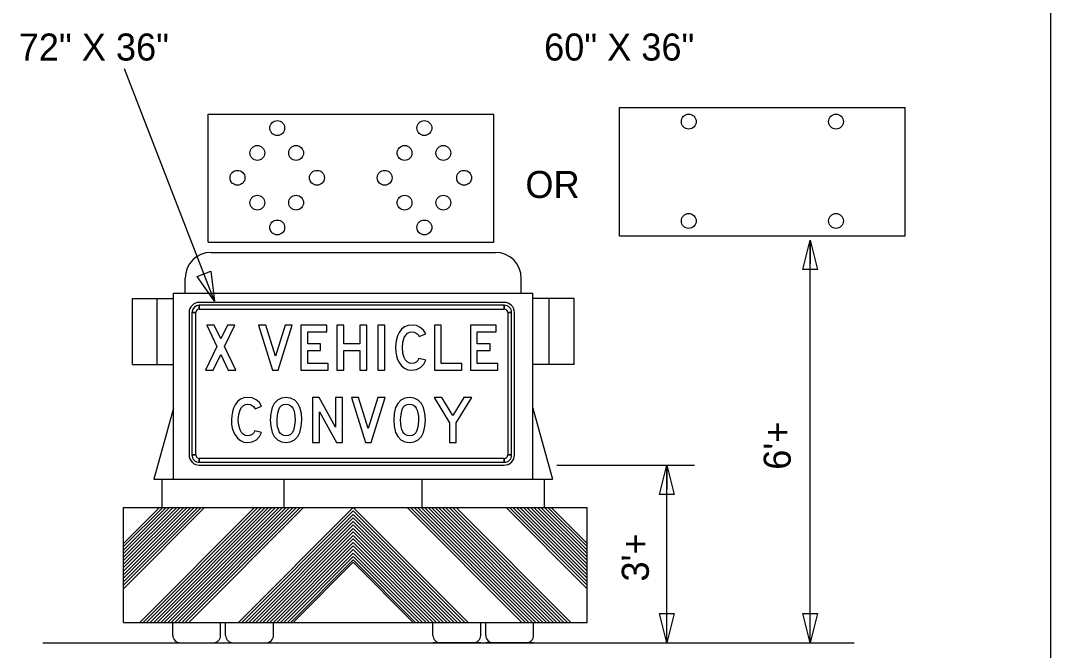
# Model space of a CAD drawing. Extents: x 1374027 to 1374537, y 380415 to 381405.
# Drawn here: x 1374118.45 to 1374141.31, y 381351.11 to 381365.09 of the extents above; entities that cross this region are included whole.
import ezdxf

# ---------------------------------------------------------------- set-up
doc = ezdxf.new("R2010")
doc.units = 0
doc.layers.add('Working Level 1', color=7, linetype='Continuous')

msp = doc.modelspace()

# ---------------------------------------------------------------- linework, layer by layer
at = {"layer": 'Working Level 1'}
for p, q in [((1374141.313, 381402.674), (1374141.313, 381297.674)), ((1374122.756, 381358.864), (1374120.755, 381364.019)), ((1374131.749, 381360.313), (1374131.749, 381363.157)), ((1374131.749, 381363.157), (1374138.092, 381363.157)), ((1374138.092, 381360.313), (1374138.092, 381363.157)), ((1374122.611, 381363.012), (1374128.954, 381363.012)), ((1374122.611, 381360.168), (1374122.611, 381363.012)), ((1374128.954, 381360.168), (1374128.954, 381363.012)), ((1374131.749, 381360.313), (1374138.092, 381360.313)), ((1374122.611, 381360.168), (1374128.954, 381360.168)), ((1374135.976, 381351.279), (1374135.976, 381360.211)), ((1374135.976, 381360.211), (1374135.976, 381359.687)), ((1374122.676, 381359.943), (1374128.99, 381359.943)), ((1374122.102, 381359.04), (1374122.102, 381359.369)), ((1374129.565, 381359.04), (1374129.565, 381359.369)), ((1374121.842, 381354.913), (1374121.842, 381359.04)), ((1374121.842, 381359.04), (1374129.825, 381359.04)), ((1374129.825, 381354.913), (1374129.825, 381359.04)), ((1374120.931, 381357.457), (1374120.931, 381358.923)), ((1374120.931, 381358.923), (1374121.842, 381358.923)), ((1374121.483, 381357.457), (1374121.483, 381358.923)), ((1374129.188, 381358.833), (1374122.416, 381358.833)), ((1374122.416, 381358.682), (1374122.416, 381358.77)), ((1374129.188, 381358.77), (1374129.188, 381358.682)), ((1374130.736, 381358.923), (1374129.825, 381358.923)), ((1374130.184, 381357.457), (1374130.184, 381358.923)), ((1374130.736, 381357.457), (1374130.736, 381358.923)), ((1374122.191, 381358.607), (1374122.191, 381355.447)), ((1374122.253, 381358.607), (1374122.341, 381358.607)), ((1374129.263, 381358.607), (1374129.351, 381358.607)), ((1374129.414, 381355.447), (1374129.414, 381358.607)), ((1374120.931, 381357.457), (1374121.842, 381357.457)), ((1374130.736, 381357.457), (1374129.825, 381357.457)), ((1374121.842, 381356.485), (1374121.41, 381354.913)), ((1374129.825, 381356.485), (1374130.256, 381354.913)), ((1374122.341, 381355.447), (1374122.253, 381355.447)), ((1374122.416, 381355.284), (1374122.416, 381355.372)), ((1374129.188, 381355.372), (1374129.188, 381355.284)), ((1374129.351, 381355.447), (1374129.263, 381355.447)), ((1374122.416, 381355.221), (1374129.188, 381355.221)), ((1374130.351, 381355.221), (1374133.413, 381355.221)), ((1374132.795, 381351.279), (1374132.795, 381355.221)), ((1374132.795, 381355.221), (1374132.795, 381354.689)), ((1374121.41, 381354.913), (1374130.256, 381354.913)), ((1374121.59, 381354.283), (1374121.59, 381354.913)), ((1374124.302, 381354.283), (1374124.302, 381354.902)), ((1374127.365, 381354.283), (1374127.365, 381354.902)), ((1374130.077, 381354.283), (1374130.077, 381354.913)), ((1374120.733, 381354.283), (1374131.028, 381354.283)), ((1374120.733, 381354.283), (1374131.028, 381354.283)), ((1374120.733, 381354.283), (1374131.028, 381354.283)), ((1374120.733, 381354.283), (1374131.028, 381354.283)), ((1374120.733, 381351.733), (1374120.733, 381354.283)), ((1374120.733, 381353.485), (1374121.531, 381354.283)), ((1374120.733, 381352.557), (1374122.459, 381354.283)), ((1374120.733, 381352.635), (1374122.38, 381354.283)), ((1374120.733, 381352.713), (1374122.302, 381354.283)), ((1374120.733, 381352.79), (1374122.225, 381354.283)), ((1374120.733, 381352.868), (1374122.147, 381354.283)), ((1374120.733, 381352.947), (1374122.069, 381354.283)), ((1374120.733, 381353.024), (1374121.992, 381354.283)), ((1374120.733, 381353.102), (1374121.914, 381354.283)), ((1374120.733, 381353.18), (1374121.836, 381354.283)), ((1374120.733, 381353.258), (1374121.758, 381354.283)), ((1374120.733, 381353.335), (1374121.681, 381354.283)), ((1374120.733, 381353.413), (1374121.603, 381354.283)), ((1374120.733, 381352.48), (1374122.534, 381354.281)), ((1374121.092, 381351.733), (1374123.642, 381354.283)), ((1374121.169, 381351.733), (1374123.719, 381354.283)), ((1374121.247, 381351.733), (1374123.797, 381354.283)), ((1374121.326, 381351.733), (1374123.875, 381354.283)), ((1374121.403, 381351.733), (1374123.952, 381354.283)), ((1374121.481, 381351.733), (1374124.03, 381354.283)), ((1374121.559, 381351.733), (1374124.109, 381354.283)), ((1374121.637, 381351.733), (1374124.187, 381354.283)), ((1374121.714, 381351.733), (1374124.264, 381354.283)), ((1374121.792, 381351.733), (1374124.342, 381354.283)), ((1374121.87, 381351.733), (1374124.42, 381354.283)), ((1374121.947, 381351.733), (1374124.497, 381354.283)), ((1374122.025, 381351.733), (1374124.575, 381354.283)), ((1374122.103, 381351.733), (1374124.652, 381354.282)), ((1374122.181, 381351.733), (1374124.731, 381354.283)), ((1374123.284, 381351.733), (1374125.833, 381354.283)), ((1374123.361, 381351.733), (1374125.833, 381354.205)), ((1374128.383, 381351.733), (1374125.833, 381354.283)), ((1374128.302, 381351.738), (1374125.833, 381354.205)), ((1374129.579, 381351.733), (1374127.03, 381354.283)), ((1374129.657, 381351.733), (1374127.108, 381354.282)), ((1374129.735, 381351.733), (1374127.185, 381354.283)), ((1374129.813, 381351.733), (1374127.263, 381354.283)), ((1374129.89, 381351.733), (1374127.34, 381354.283)), ((1374129.968, 381351.733), (1374127.418, 381354.283)), ((1374130.046, 381351.733), (1374127.497, 381354.283)), ((1374130.123, 381351.733), (1374127.574, 381354.283)), ((1374130.201, 381351.733), (1374127.652, 381354.283)), ((1374130.28, 381351.733), (1374127.73, 381354.283)), ((1374130.358, 381351.733), (1374127.808, 381354.283)), ((1374130.435, 381351.733), (1374127.885, 381354.283)), ((1374130.513, 381351.733), (1374127.963, 381354.283)), ((1374130.591, 381351.733), (1374128.041, 381354.283)), ((1374130.668, 381351.733), (1374128.119, 381354.283)), ((1374131.028, 381352.48), (1374129.226, 381354.281)), ((1374131.028, 381352.557), (1374129.302, 381354.283)), ((1374131.028, 381352.635), (1374129.38, 381354.283)), ((1374131.028, 381352.713), (1374129.458, 381354.283)), ((1374131.028, 381352.79), (1374129.535, 381354.283)), ((1374131.028, 381352.868), (1374129.613, 381354.283)), ((1374131.028, 381352.947), (1374129.691, 381354.283)), ((1374131.028, 381353.024), (1374129.768, 381354.283)), ((1374131.028, 381353.102), (1374129.846, 381354.283)), ((1374131.028, 381353.18), (1374129.924, 381354.283)), ((1374131.028, 381353.258), (1374130.002, 381354.283)), ((1374131.028, 381353.335), (1374130.079, 381354.283)), ((1374131.028, 381353.413), (1374130.157, 381354.283)), ((1374131.028, 381353.485), (1374130.23, 381354.283)), ((1374131.028, 381351.733), (1374131.028, 381354.283)), ((1374123.439, 381351.733), (1374125.833, 381354.127)), ((1374123.517, 381351.733), (1374125.833, 381354.049)), ((1374123.594, 381351.733), (1374125.833, 381353.972)), ((1374128.228, 381351.733), (1374125.833, 381354.127)), ((1374128.15, 381351.733), (1374125.833, 381354.049)), ((1374128.073, 381351.733), (1374125.833, 381353.972)), ((1374123.672, 381351.733), (1374125.833, 381353.894)), ((1374123.751, 381351.733), (1374125.833, 381353.816)), ((1374123.828, 381351.733), (1374125.833, 381353.739)), ((1374127.995, 381351.733), (1374125.833, 381353.894)), ((1374127.917, 381351.733), (1374125.833, 381353.816)), ((1374127.84, 381351.733), (1374125.833, 381353.739)), ((1374123.906, 381351.733), (1374125.833, 381353.661)), ((1374123.984, 381351.733), (1374125.833, 381353.583)), ((1374124.062, 381351.733), (1374125.833, 381353.505)), ((1374127.762, 381351.733), (1374125.833, 381353.661)), ((1374127.684, 381351.733), (1374125.833, 381353.583)), ((1374127.605, 381351.733), (1374125.833, 381353.505)), ((1374124.139, 381351.733), (1374125.833, 381353.428)), ((1374124.217, 381351.733), (1374125.833, 381353.35)), ((1374124.295, 381351.733), (1374125.833, 381353.272)), ((1374127.528, 381351.733), (1374125.833, 381353.428)), ((1374127.45, 381351.733), (1374125.833, 381353.35)), ((1374127.372, 381351.733), (1374125.833, 381353.272)), ((1374124.372, 381351.733), (1374125.833, 381353.195)), ((1374124.45, 381351.733), (1374125.833, 381353.117)), ((1374124.515, 381351.748), (1374125.833, 381353.066)), ((1374127.295, 381351.733), (1374125.833, 381353.195)), ((1374127.217, 381351.733), (1374125.833, 381353.117)), ((1374127.167, 381351.733), (1374125.833, 381353.066)), ((1374120.733, 381351.733), (1374131.028, 381351.733)), ((1374120.733, 381351.733), (1374131.028, 381351.733)), ((1374120.733, 381351.733), (1374131.028, 381351.733)), ((1374120.733, 381351.733), (1374131.028, 381351.733)), ((1374121.827, 381351.444), (1374121.827, 381351.733)), ((1374122.89, 381351.444), (1374122.89, 381351.733)), ((1374123, 381351.444), (1374123, 381351.733)), ((1374124.064, 381351.444), (1374124.064, 381351.733)), ((1374127.603, 381351.444), (1374127.603, 381351.733)), ((1374128.666, 381351.444), (1374128.666, 381351.733)), ((1374128.776, 381351.444), (1374128.776, 381351.733)), ((1374129.84, 381351.444), (1374129.84, 381351.733)), ((1374118.945, 381351.279), (1374136.956, 381351.279)), ((1374121.827, 381351.279), (1374122.89, 381351.279)), ((1374121.827, 381351.279), (1374122.89, 381351.279)), ((1374121.827, 381351.279), (1374122.89, 381351.279)), ((1374121.827, 381351.279), (1374122.89, 381351.279)), ((1374123, 381351.279), (1374124.064, 381351.279)), ((1374123, 381351.279), (1374124.064, 381351.279)), ((1374123, 381351.279), (1374124.064, 381351.279)), ((1374123, 381351.279), (1374124.064, 381351.279)), ((1374128.666, 381351.279), (1374127.603, 381351.279)), ((1374128.666, 381351.279), (1374127.603, 381351.279)), ((1374128.666, 381351.279), (1374127.603, 381351.279)), ((1374128.666, 381351.279), (1374127.603, 381351.279)), ((1374129.84, 381351.279), (1374128.776, 381351.279)), ((1374129.84, 381351.279), (1374128.776, 381351.279)), ((1374129.84, 381351.279), (1374128.776, 381351.279)), ((1374129.84, 381351.279), (1374128.776, 381351.279))]:
    msp.add_line(p, q, dxfattribs=at)
for points in [[(1374135.814, 381359.561), (1374135.976, 381360.211), (1374136.139, 381359.561)], [(1374122.672, 381359.529), (1374122.756, 381358.864), (1374122.369, 381359.411)], [(1374129.188, 381358.77), (1374122.416, 381358.77), (1374122.416, 381358.682), (1374129.188, 381358.682), (1374129.188, 381358.77)], [(1374122.253, 381358.607), (1374122.253, 381355.447), (1374122.341, 381355.447), (1374122.341, 381358.607), (1374122.253, 381358.607)], [(1374129.351, 381355.447), (1374129.351, 381358.607), (1374129.263, 381358.607), (1374129.263, 381355.447), (1374129.351, 381355.447)], [(1374123.227, 381357.328), (1374122.977, 381357.853), (1374123.206, 381358.331), (1374123.039, 381358.331), (1374122.893, 381358.028), (1374122.749, 381358.331), (1374122.581, 381358.331), (1374122.809, 381357.852), (1374122.557, 381357.328), (1374122.725, 381357.328), (1374122.892, 381357.677), (1374123.059, 381357.328)], [(1374124.48, 381358.331), (1374124.322, 381358.331), (1374124.106, 381357.638), (1374123.891, 381358.331), (1374123.733, 381358.331), (1374124.044, 381357.328), (1374124.168, 381357.328)], [(1374125.28, 381357.479), (1374124.825, 381357.479), (1374124.825, 381357.763), (1374125.109, 381357.763), (1374125.109, 381357.915), (1374124.825, 381357.915), (1374124.825, 381358.18), (1374125.249, 381358.18), (1374125.249, 381358.331), (1374124.673, 381358.331), (1374124.673, 381357.328), (1374125.28, 381357.328)], [(1374126.135, 381357.328), (1374126.135, 381358.331), (1374125.984, 381358.331), (1374125.984, 381357.915), (1374125.624, 381357.915), (1374125.624, 381358.331), (1374125.473, 381358.331), (1374125.473, 381357.328), (1374125.624, 381357.328), (1374125.624, 381357.763), (1374125.984, 381357.763), (1374125.984, 381357.328)], [(1374126.533, 381357.328), (1374126.533, 381358.331), (1374126.382, 381358.331), (1374126.382, 381357.328)], [(1374127.443, 381357.551), (1374127.292, 381357.589), (1374127.269, 381357.545), (1374127.233, 381357.51), (1374127.186, 381357.487), (1374127.133, 381357.479), (1374127.081, 381357.487), (1374127.035, 381357.511), (1374126.997, 381357.551), (1374126.967, 381357.607), (1374126.935, 381357.71), (1374126.925, 381357.83), (1374126.936, 381357.95), (1374126.968, 381358.053), (1374126.999, 381358.108), (1374127.038, 381358.148), (1374127.084, 381358.172), (1374127.138, 381358.18), (1374127.188, 381358.173), (1374127.234, 381358.152), (1374127.272, 381358.119), (1374127.298, 381358.077), (1374127.443, 381358.134), (1374127.394, 381358.215), (1374127.323, 381358.277), (1374127.236, 381358.318), (1374127.141, 381358.331), (1374127.052, 381358.321), (1374126.975, 381358.289), (1374126.909, 381358.237), (1374126.855, 381358.164), (1374126.819, 381358.091), (1374126.794, 381358.012), (1374126.779, 381357.925), (1374126.774, 381357.83), (1374126.779, 381357.736), (1374126.794, 381357.649), (1374126.819, 381357.569), (1374126.854, 381357.497), (1374126.907, 381357.423), (1374126.972, 381357.37), (1374127.048, 381357.338), (1374127.136, 381357.328), (1374127.238, 381357.343), (1374127.329, 381357.39), (1374127.401, 381357.461)], [(1374128.243, 381357.328), (1374128.243, 381357.479), (1374127.787, 381357.479), (1374127.787, 381358.331), (1374127.636, 381358.331), (1374127.636, 381357.328)], [(1374129.042, 381357.479), (1374128.587, 381357.479), (1374128.587, 381357.763), (1374128.871, 381357.763), (1374128.871, 381357.915), (1374128.587, 381357.915), (1374128.587, 381358.18), (1374129.011, 381358.18), (1374129.011, 381358.331), (1374128.436, 381358.331), (1374128.436, 381357.328), (1374129.042, 381357.328)], [(1374123.799, 381355.946), (1374123.647, 381355.984), (1374123.625, 381355.94), (1374123.588, 381355.905), (1374123.541, 381355.882), (1374123.489, 381355.874), (1374123.436, 381355.882), (1374123.391, 381355.906), (1374123.353, 381355.946), (1374123.322, 381356.002), (1374123.291, 381356.105), (1374123.281, 381356.224), (1374123.291, 381356.345), (1374123.323, 381356.448), (1374123.355, 381356.503), (1374123.394, 381356.543), (1374123.44, 381356.567), (1374123.494, 381356.575), (1374123.544, 381356.568), (1374123.59, 381356.547), (1374123.628, 381356.514), (1374123.654, 381356.472), (1374123.799, 381356.529), (1374123.75, 381356.61), (1374123.678, 381356.672), (1374123.591, 381356.712), (1374123.496, 381356.726), (1374123.408, 381356.715), (1374123.331, 381356.684), (1374123.265, 381356.632), (1374123.21, 381356.559), (1374123.175, 381356.486), (1374123.15, 381356.407), (1374123.135, 381356.319), (1374123.13, 381356.225), (1374123.134, 381356.131), (1374123.149, 381356.044), (1374123.174, 381355.964), (1374123.209, 381355.892), (1374123.263, 381355.818), (1374123.328, 381355.765), (1374123.404, 381355.733), (1374123.491, 381355.723), (1374123.593, 381355.738), (1374123.685, 381355.785), (1374123.756, 381355.856)], [(1374124.692, 381356.225), (1374124.682, 381356.368), (1374124.651, 381356.502), (1374124.606, 381356.593), (1374124.534, 381356.664), (1374124.443, 381356.71), (1374124.341, 381356.726), (1374124.239, 381356.71), (1374124.149, 381356.664), (1374124.077, 381356.592), (1374124.032, 381356.501), (1374124.002, 381356.367), (1374123.992, 381356.225), (1374124.002, 381356.083), (1374124.032, 381355.949), (1374124.077, 381355.857), (1374124.149, 381355.786), (1374124.239, 381355.739), (1374124.341, 381355.723), (1374124.443, 381355.738), (1374124.533, 381355.785), (1374124.605, 381355.856), (1374124.65, 381355.947), (1374124.681, 381356.081)], [(1374125.595, 381355.723), (1374125.595, 381356.726), (1374125.443, 381356.726), (1374125.443, 381356.067), (1374125.078, 381356.726), (1374124.932, 381356.726), (1374124.932, 381355.723), (1374125.084, 381355.723), (1374125.084, 381356.403), (1374125.461, 381355.723)], [(1374126.541, 381356.726), (1374126.383, 381356.726), (1374126.167, 381356.033), (1374125.953, 381356.726), (1374125.794, 381356.726), (1374126.105, 381355.723), (1374126.23, 381355.723)], [(1374127.435, 381356.225), (1374127.425, 381356.368), (1374127.394, 381356.502), (1374127.349, 381356.593), (1374127.277, 381356.664), (1374127.186, 381356.71), (1374127.084, 381356.726), (1374126.982, 381356.71), (1374126.892, 381356.664), (1374126.821, 381356.592), (1374126.776, 381356.501), (1374126.745, 381356.367), (1374126.735, 381356.225), (1374126.745, 381356.083), (1374126.776, 381355.949), (1374126.821, 381355.857), (1374126.892, 381355.786), (1374126.982, 381355.739), (1374127.084, 381355.723), (1374127.186, 381355.738), (1374127.277, 381355.785), (1374127.348, 381355.856), (1374127.393, 381355.947), (1374127.424, 381356.081)], [(1374128.469, 381356.726), (1374128.291, 381356.726), (1374128.045, 381356.326), (1374127.804, 381356.726), (1374127.628, 381356.726), (1374127.969, 381356.162), (1374127.969, 381355.723), (1374128.12, 381355.723), (1374128.12, 381356.158)], [(1374124.541, 381356.224), (1374124.532, 381356.103), (1374124.505, 381355.989), (1374124.481, 381355.942), (1374124.443, 381355.905), (1374124.396, 381355.882), (1374124.342, 381355.874), (1374124.295, 381355.88), (1374124.255, 381355.896), (1374124.221, 381355.923), (1374124.193, 381355.962), (1374124.171, 381356.011), (1374124.155, 381356.071), (1374124.146, 381356.142), (1374124.143, 381356.224), (1374124.152, 381356.346), (1374124.179, 381356.459), (1374124.202, 381356.506), (1374124.24, 381356.543), (1374124.288, 381356.567), (1374124.342, 381356.575), (1374124.389, 381356.569), (1374124.429, 381356.553), (1374124.463, 381356.525), (1374124.491, 381356.487), (1374124.512, 381356.438), (1374124.528, 381356.378), (1374124.537, 381356.306)], [(1374127.284, 381356.224), (1374127.275, 381356.103), (1374127.248, 381355.989), (1374127.224, 381355.942), (1374127.186, 381355.905), (1374127.139, 381355.882), (1374127.086, 381355.874), (1374127.038, 381355.88), (1374126.998, 381355.896), (1374126.964, 381355.923), (1374126.936, 381355.962), (1374126.914, 381356.011), (1374126.899, 381356.071), (1374126.889, 381356.142), (1374126.886, 381356.224), (1374126.895, 381356.346), (1374126.922, 381356.459), (1374126.946, 381356.506), (1374126.983, 381356.543), (1374127.031, 381356.567), (1374127.086, 381356.575), (1374127.132, 381356.569), (1374127.172, 381356.553), (1374127.206, 381356.525), (1374127.234, 381356.487), (1374127.255, 381356.438), (1374127.271, 381356.378), (1374127.28, 381356.306)], [(1374122.416, 381355.284), (1374129.188, 381355.284), (1374129.188, 381355.372), (1374122.416, 381355.372), (1374122.416, 381355.284)], [(1374132.633, 381354.571), (1374132.795, 381355.221), (1374132.958, 381354.571)], [(1374132.958, 381351.929), (1374132.795, 381351.279), (1374132.633, 381351.929)], [(1374136.139, 381351.929), (1374135.976, 381351.279), (1374135.814, 381351.929)]]:
    msp.add_lwpolyline(points, close=True, dxfattribs=at)
for centre in [(1374124.146, 381362.701), (1374127.414, 381362.701), (1374133.284, 381362.846), (1374136.552, 381362.846), (1374123.705, 381362.15), (1374124.566, 381362.15), (1374126.973, 381362.15), (1374127.834, 381362.15), (1374123.264, 381361.598), (1374125.028, 381361.598), (1374126.532, 381361.598), (1374128.296, 381361.598), (1374123.705, 381361.047), (1374124.566, 381361.047), (1374126.973, 381361.047), (1374127.834, 381361.047), (1374133.284, 381360.641), (1374136.552, 381360.641), (1374124.146, 381360.496), (1374127.414, 381360.496)]:
    msp.add_circle(centre, 0.165, dxfattribs=at)
for centre, radius, start, end in [((1374122.676, 381359.369), 0.574, 90, 180), ((1374128.991, 381359.369), 0.574, 0, 90), ((1374122.416, 381358.607), 0.226, 90.0002, 179.9998), ((1374122.416, 381358.607), 0.163, 90.0002, 179.9998), ((1374129.188, 381358.607), 0.226, 0, 90.0002), ((1374129.188, 381358.607), 0.163, 0, 90.0002), ((1374122.416, 381358.607), 0.0752, 90.0002, 179.9998), ((1374129.188, 381358.607), 0.0752, 0, 90.0002), ((1374122.416, 381355.447), 0.226, 179.9998, 270.0001), ((1374122.416, 381355.447), 0.163, 179.9998, 270.0001), ((1374122.416, 381355.447), 0.0752, 179.9998, 270.0001), ((1374129.188, 381355.447), 0.226, 270.0001, 0.0003), ((1374129.188, 381355.447), 0.163, 270.0001, 0.0003), ((1374129.188, 381355.447), 0.0752, 270.0001, 0.0003), ((1374121.992, 381351.444), 0.165, 180, 270), ((1374122.725, 381351.444), 0.165, 270, 0), ((1374123.165, 381351.444), 0.165, 180, 270), ((1374123.899, 381351.444), 0.165, 270, 0), ((1374127.768, 381351.444), 0.165, 180, 270), ((1374128.501, 381351.444), 0.165, 270, 0), ((1374128.941, 381351.444), 0.165, 180, 270), ((1374129.675, 381351.444), 0.165, 270, 0)]:
    msp.add_arc(centre, radius, start, end, dxfattribs=at)

# ---------------------------------------------------------------- texts
for s, rotation, p in [('72" X 36"', 0, (1374118.407, 381364.2)), ('60" X 36"', 0, (1374130.072, 381364.2)), ("6'+", 90, (1374135.547, 381355.119)), ("3'+", 90, (1374132.397, 381352.639))]:
    msp.add_text(s, height=0.6, rotation=rotation, dxfattribs=at).set_placement(p)
msp.add_text('OR', height=0.6, dxfattribs=at).set_placement((1374129.657, 381361.15))

doc.saveas('drawing.dxf')
